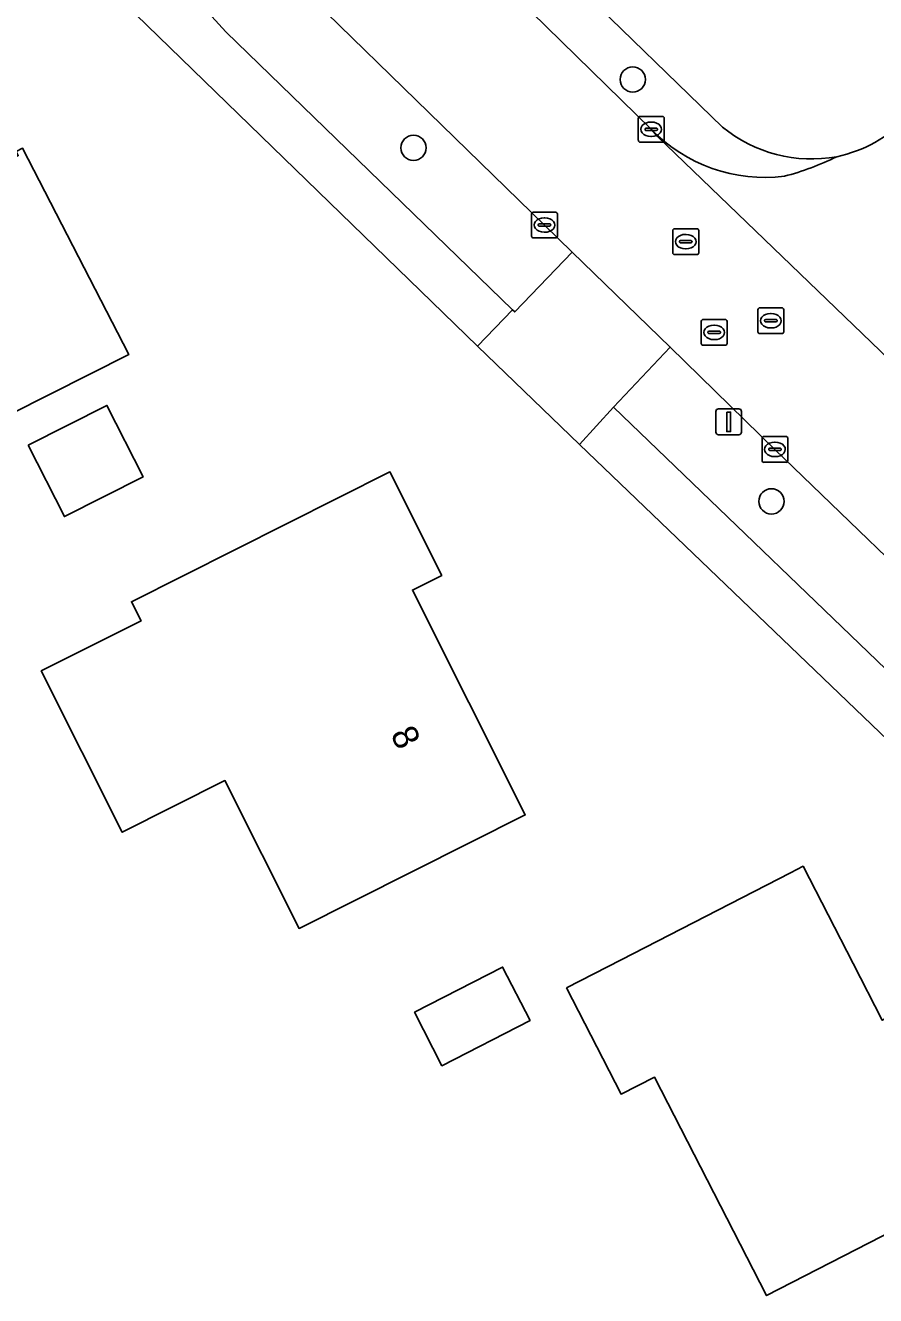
# Model space of a CAD drawing. Extents: x 162722 to 165104, y 384719 to 386284.
# Drawn here: x 163705.77 to 163738.67, y 384880.98 to 384930.12 of the extents above; entities that cross this region are included whole.
import ezdxf

# ---------------------------------------------------------------- set-up
doc = ezdxf.new("R2010")
doc.units = 0
for name, color, linetype in [('IMGEO_Boom', 7, 'Continuous'), ('IMGEO_Erf', 7, 'Continuous'), ('IMGEO_Groenvoorziening', 7, 'Continuous'), ('IMGEO_Kolk', 7, 'Continuous'), ('IMGEO_Lichtmast', 7, 'Continuous'), ('IMGEO_Pand', 7, 'Continuous'), ('IMGEO_Pand_nummerreeks', 7, 'Continuous'), ('IMGEO_Parkeervlak_open', 7, 'Continuous'), ('IMGEO_Rijbaan_lokaal_open', 7, 'Continuous'), ('IMGEO_Rioolput', 7, 'Continuous'), ('IMGEO_Voetpad_open', 7, 'Continuous')]:
    doc.layers.add(name, color=color, linetype=linetype)

msp = doc.modelspace()

# ---------------------------------------------------------------- linework, layer by layer
at = {"layer": 'IMGEO_Boom'}
for centre in [(163729.27, 384928.029), (163720.787, 384925.386), (163734.636, 384911.709)]:
    msp.add_circle(centre, 0.489, dxfattribs=at)
at = {"layer": 'IMGEO_Erf'}
for points in [[(163743.466, 384898.114), (163739.775, 384901.866), (163727.21, 384913.912), (163723.266, 384917.713), (163708.711, 384931.843), (163707.497, 384933.071), (163703.684, 384937.056), (163680.028, 384919.248)], [(163721.477, 384937.136), (163732.746, 384926.182)]]:
    msp.add_lwpolyline(points, dxfattribs=at)
for points in [[(163700.576, 384912.76), (163698.165, 384917.548), (163690.367, 384913.622), (163687.312, 384919.691), (163692.94, 384922.524), (163693.071, 384922.265), (163695.08, 384923.277), (163694.949, 384923.535), (163702.295, 384927.318), (163703.875, 384924.249), (163705.494, 384925.083), (163705.411, 384925.243), (163705.661, 384925.37), (163709.772, 384917.389)], [(163705.88, 384913.883), (163708.922, 384915.423), (163710.322, 384912.657), (163707.28, 384911.117)], [(163716.362, 384895.186), (163713.493, 384900.904), (163709.515, 384898.909), (163706.384, 384905.149), (163710.244, 384907.086), (163709.872, 384907.826), (163719.873, 384912.845), (163721.881, 384908.845), (163720.746, 384908.276), (163725.112, 384899.577)], [(163726.707, 384892.894), (163728.818, 384893.978), (163735.374, 384897.343), (163735.863, 384897.594), (163737.794, 384893.832), (163738.923, 384891.634), (163740.951, 384892.675), (163744.345, 384886.063), (163734.448, 384880.983), (163730.109, 384889.438), (163728.82, 384888.776)], [(163724.237, 384893.694), (163725.297, 384891.628), (163721.888, 384889.878), (163720.828, 384891.944)]]:
    msp.add_lwpolyline(points, close=True, dxfattribs=at)
for centre, radius, start, end in [((163735.945, 384930.498), 5.594, 282.6076, 314.948), ((163736.202, 384930.43), 5.476, 230.8666, 280.1356)]:
    msp.add_arc(centre, radius, start, end, dxfattribs=at)
at = {"layer": 'IMGEO_Groenvoorziening'}
msp.add_lwpolyline([(163706.129, 384938.825), (163705.921, 384938.688), (163709.613, 384934.17), (163713.526, 384929.868), (163724.619, 384919.117), (163724.703, 384919.039), (163726.925, 384921.347), (163725.854, 384922.399), (163712.452, 384935.454), (163709.401, 384938.391)], dxfattribs=at)
msp.add_lwpolyline([(163743.27, 384905.487), (163742.334, 384906.411), (163734.773, 384913.719), (163730.72, 384917.677), (163728.529, 384915.354), (163741.103, 384903.254)], close=True, dxfattribs=at)
at = {"layer": 'IMGEO_Kolk'}
for p, q in [((163729.486, 384925.677), (163729.486, 384926.529)), ((163729.561, 384926.603), (163730.413, 384926.603)), ((163730.487, 384926.529), (163730.487, 384925.677)), ((163729.745, 384926.097), (163729.745, 384926.109)), ((163730.183, 384926.06), (163729.785, 384926.06)), ((163729.788, 384926.146), (163730.186, 384926.146)), ((163729.974, 384926.383), (163729.999, 384926.383)), ((163730.229, 384926.109), (163730.229, 384926.097)), ((163730.413, 384925.603), (163729.561, 384925.603)), ((163729.997, 384925.823), (163729.972, 384925.823)), ((163725.353, 384921.973), (163725.353, 384922.825)), ((163725.428, 384922.899), (163726.28, 384922.899)), ((163725.841, 384922.679), (163725.866, 384922.679)), ((163726.354, 384922.825), (163726.354, 384921.973)), ((163725.612, 384922.393), (163725.612, 384922.405)), ((163726.05, 384922.356), (163725.652, 384922.356)), ((163725.655, 384922.442), (163726.053, 384922.442)), ((163725.864, 384922.119), (163725.839, 384922.119)), ((163726.096, 384922.405), (163726.096, 384922.393)), ((163726.28, 384921.899), (163725.428, 384921.899)), ((163734.272, 384913.293), (163734.272, 384914.145)), ((163734.347, 384914.219), (163735.199, 384914.219)), ((163735.273, 384914.145), (163735.273, 384913.293)), ((163734.531, 384913.713), (163734.531, 384913.725)), ((163734.969, 384913.676), (163734.571, 384913.676)), ((163734.574, 384913.762), (163734.972, 384913.762)), ((163734.76, 384913.999), (163734.785, 384913.999)), ((163735.015, 384913.725), (163735.015, 384913.713)), ((163735.199, 384913.219), (163734.347, 384913.219)), ((163734.783, 384913.439), (163734.758, 384913.439))]:
    msp.add_line(p, q, dxfattribs=at)
for points in [[(163729.486, 384925.677), (163729.486, 384926.529)], [(163729.561, 384926.603), (163730.413, 384926.603)], [(163730.487, 384926.529), (163730.487, 384925.677)], [(163730.413, 384925.603), (163729.561, 384925.603)], [(163725.353, 384921.973), (163725.353, 384922.825)], [(163725.428, 384922.899), (163726.28, 384922.899)], [(163726.354, 384922.825), (163726.354, 384921.973)], [(163726.28, 384921.899), (163725.428, 384921.899)], [(163734.272, 384913.293), (163734.272, 384914.145)], [(163734.347, 384914.219), (163735.199, 384914.219)], [(163735.273, 384914.145), (163735.273, 384913.293)], [(163735.199, 384913.219), (163734.347, 384913.219)]]:
    msp.add_lwpolyline(points, dxfattribs=at)
for centre, radius, start, end in [((163729.563, 384926.527), 0.0765, 91.552, 178.448), ((163729.563, 384926.527), 0.0765, 91.552, 178.448), ((163730.411, 384926.527), 0.0765, 1.552, 88.448), ((163730.411, 384926.527), 0.0765, 1.552, 88.448), ((163729.785, 384926.106), 0.0403, 85.8775, 175.7526), ((163729.782, 384926.096), 0.0366, 178.938, 274.7102), ((163730.186, 384926.103), 0.043, 264.8664, 352.4533), ((163730.19, 384926.108), 0.0386, 1.7309, 96.639), ((163729.563, 384925.679), 0.0765, 181.552, 268.448), ((163729.563, 384925.679), 0.0765, 181.552, 268.448), ((163730.411, 384925.679), 0.0765, 271.552, 358.448), ((163730.411, 384925.679), 0.0765, 271.552, 358.448), ((163725.43, 384922.823), 0.0765, 91.552, 178.448), ((163725.43, 384922.823), 0.0765, 91.552, 178.448), ((163726.278, 384922.823), 0.0765, 1.552, 88.448), ((163726.278, 384922.823), 0.0765, 1.552, 88.448), ((163725.652, 384922.402), 0.0403, 85.8775, 175.7526), ((163725.649, 384922.392), 0.0366, 178.938, 274.7102), ((163726.053, 384922.399), 0.043, 264.8664, 352.4533), ((163726.057, 384922.404), 0.0386, 1.7309, 96.639), ((163725.43, 384921.975), 0.0765, 181.552, 268.448), ((163725.43, 384921.975), 0.0765, 181.552, 268.448), ((163726.278, 384921.975), 0.0765, 271.552, 358.448), ((163726.278, 384921.975), 0.0765, 271.552, 358.448), ((163734.349, 384914.143), 0.0765, 91.552, 178.448), ((163734.349, 384914.143), 0.0765, 91.552, 178.448), ((163735.197, 384914.143), 0.0765, 1.552, 88.448), ((163735.197, 384914.143), 0.0765, 1.552, 88.448), ((163734.571, 384913.722), 0.0403, 85.8775, 175.7526), ((163734.568, 384913.712), 0.0366, 178.938, 274.7102), ((163734.972, 384913.719), 0.043, 264.8664, 352.4533), ((163734.976, 384913.724), 0.0386, 1.7309, 96.639), ((163734.349, 384913.295), 0.0765, 181.552, 268.448), ((163734.349, 384913.295), 0.0765, 181.552, 268.448), ((163735.197, 384913.295), 0.0765, 271.552, 358.448), ((163735.197, 384913.295), 0.0765, 271.552, 358.448)]:
    msp.add_arc(centre, radius, start, end, dxfattribs=at)
for centre, major_axis, ratio, start_param, end_param in [((163729.973, 384926.103), (-0.387, 0.002), 0.722429, 4.712389, 7.853982), ((163729.998, 384926.103), (-0.39, 0.002), 0.717154, 1.570796, 4.712389), ((163725.84, 384922.399), (-0.387, 0.002), 0.722429, 4.712389, 7.853982), ((163725.865, 384922.399), (-0.39, 0.002), 0.717154, 1.570796, 4.712389), ((163734.759, 384913.719), (-0.387, 0.002), 0.722429, 4.712389, 7.853982), ((163734.784, 384913.719), (-0.39, 0.002), 0.717154, 1.570796, 4.712389)]:
    msp.add_ellipse(centre, major_axis=major_axis, ratio=ratio, start_param=start_param, end_param=end_param, dxfattribs=at)
at = {"layer": 'IMGEO_Lichtmast'}
for p, q in [((163732.487, 384914.386), (163732.487, 384915.186)), ((163732.487, 384915.186), (163732.487, 384914.386)), ((163732.587, 384915.286), (163733.377, 384915.286)), ((163733.377, 384915.286), (163732.587, 384915.286)), ((163733.477, 384915.186), (163733.477, 384914.386)), ((163733.477, 384914.386), (163733.477, 384915.186)), ((163733.377, 384914.286), (163732.587, 384914.286)), ((163732.587, 384914.286), (163733.377, 384914.286))]:
    msp.add_line(p, q, dxfattribs=at)
msp.add_lwpolyline([(163732.907, 384915.161), (163733.057, 384915.161), (163733.057, 384914.411), (163732.907, 384914.411), (163732.907, 384915.161)], dxfattribs=at)
for centre, start, end in [((163732.587, 384915.186), 90, 180), ((163732.587, 384915.186), 90, 180), ((163733.377, 384915.186), 0, 90), ((163733.377, 384915.186), 360, 90), ((163732.587, 384914.386), 180, 270), ((163732.587, 384914.386), 180, 270), ((163733.377, 384914.386), 270, 0), ((163733.377, 384914.386), 270, 0)]:
    msp.add_arc(centre, 0.1, start, end, dxfattribs=at)
at = {"layer": 'IMGEO_Pand'}
for points in [[(163694.949, 384923.535), (163695.08, 384923.277), (163693.071, 384922.265), (163692.94, 384922.524), (163687.312, 384919.691), (163690.367, 384913.622), (163698.165, 384917.548), (163700.576, 384912.76), (163709.772, 384917.389), (163705.661, 384925.37), (163705.411, 384925.243), (163705.494, 384925.083), (163703.875, 384924.249), (163702.295, 384927.318)], [(163705.88, 384913.883), (163707.28, 384911.117), (163710.322, 384912.657), (163708.922, 384915.423)], [(163725.112, 384899.577), (163720.746, 384908.276), (163721.881, 384908.845), (163719.873, 384912.845), (163709.872, 384907.826), (163710.244, 384907.086), (163706.384, 384905.149), (163709.515, 384898.909), (163713.493, 384900.904), (163716.362, 384895.186)], [(163726.707, 384892.894), (163728.82, 384888.776), (163730.109, 384889.438), (163734.448, 384880.983), (163744.345, 384886.063), (163740.951, 384892.675), (163738.923, 384891.634), (163737.794, 384893.832), (163735.863, 384897.594), (163735.374, 384897.343), (163728.818, 384893.978)], [(163720.828, 384891.944), (163721.888, 384889.878), (163725.297, 384891.628), (163724.237, 384893.694)]]:
    msp.add_lwpolyline(points, close=True, dxfattribs=at)
at = {"layer": 'IMGEO_Parkeervlak_open'}
msp.add_lwpolyline([(163732.746, 384926.182), (163721.477, 384937.136), (163720.131, 384935.757), (163729.987, 384926.103)], dxfattribs=at)
for centre, radius, start, end in [((163734.383, 384930.362), 6.121, 224.0915, 277.0947), ((163736.202, 384930.43), 5.476, 230.8666, 280.1356), ((163732.389, 384934.822), 10.887, 284.6322, 296.0269)]:
    msp.add_arc(centre, radius, start, end, dxfattribs=at)
at = {"layer": 'IMGEO_Rijbaan_lokaal_open'}
for points in [[(163729.987, 384926.103), (163720.131, 384935.757), (163717.931, 384937.92), (163716.552, 384939.414), (163715.161, 384941.031)], [(163712.452, 384935.454), (163725.854, 384922.399), (163726.925, 384921.347), (163730.72, 384917.677), (163734.773, 384913.719), (163742.334, 384906.411), (163743.27, 384905.487), (163747.074, 384901.756), (163754.848, 384894.139), (163760.946, 384888.265)], [(163767.038, 384890.055), (163760.158, 384896.76), (163755.5, 384901.311), (163743.694, 384912.858), (163742.747, 384913.794), (163742.638, 384913.882), (163730.224, 384925.82), (163729.987, 384926.103)], [(163729.987, 384926.103), (163730.224, 384925.82), (163742.638, 384913.882), (163742.747, 384913.794)]]:
    msp.add_lwpolyline(points, dxfattribs=at)
for centre, radius, start, end in [((163735.945, 384930.498), 5.594, 282.6076, 314.948), ((163734.383, 384930.362), 6.121, 224.0915, 277.0947), ((163732.389, 384934.822), 10.887, 284.6322, 296.0269)]:
    msp.add_arc(centre, radius, start, end, dxfattribs=at)
at = {"layer": 'IMGEO_Rioolput'}
for p, q in [((163730.82, 384921.33), (163730.82, 384922.182)), ((163730.895, 384922.256), (163731.747, 384922.256)), ((163731.308, 384922.036), (163731.333, 384922.036)), ((163731.821, 384922.182), (163731.821, 384921.33)), ((163731.079, 384921.75), (163731.079, 384921.762)), ((163731.517, 384921.713), (163731.119, 384921.713)), ((163731.122, 384921.799), (163731.52, 384921.799)), ((163731.563, 384921.762), (163731.563, 384921.75)), ((163731.747, 384921.256), (163730.895, 384921.256)), ((163731.331, 384921.476), (163731.306, 384921.476)), ((163734.114, 384918.271), (163734.114, 384919.123)), ((163734.189, 384919.197), (163735.041, 384919.197)), ((163735.115, 384919.123), (163735.115, 384918.271)), ((163731.922, 384917.82), (163731.922, 384918.672)), ((163731.997, 384918.746), (163732.849, 384918.746)), ((163732.923, 384918.672), (163732.923, 384917.82)), ((163734.373, 384918.691), (163734.373, 384918.703)), ((163734.811, 384918.654), (163734.413, 384918.654)), ((163734.416, 384918.74), (163734.814, 384918.74)), ((163734.602, 384918.977), (163734.627, 384918.977)), ((163734.857, 384918.703), (163734.857, 384918.691)), ((163732.181, 384918.24), (163732.181, 384918.252)), ((163732.619, 384918.203), (163732.221, 384918.203)), ((163732.224, 384918.289), (163732.622, 384918.289)), ((163732.41, 384918.526), (163732.435, 384918.526)), ((163732.665, 384918.252), (163732.665, 384918.24)), ((163735.041, 384918.197), (163734.189, 384918.197)), ((163734.625, 384918.417), (163734.6, 384918.417)), ((163732.849, 384917.746), (163731.997, 384917.746)), ((163732.433, 384917.966), (163732.408, 384917.966))]:
    msp.add_line(p, q, dxfattribs=at)
for points in [[(163730.82, 384921.33), (163730.82, 384922.182)], [(163730.895, 384922.256), (163731.747, 384922.256)], [(163731.821, 384922.182), (163731.821, 384921.33)], [(163731.747, 384921.256), (163730.895, 384921.256)], [(163734.114, 384918.271), (163734.114, 384919.123)], [(163734.189, 384919.197), (163735.041, 384919.197)], [(163735.115, 384919.123), (163735.115, 384918.271)], [(163731.922, 384917.82), (163731.922, 384918.672)], [(163731.997, 384918.746), (163732.849, 384918.746)], [(163732.923, 384918.672), (163732.923, 384917.82)], [(163735.041, 384918.197), (163734.189, 384918.197)], [(163732.849, 384917.746), (163731.997, 384917.746)]]:
    msp.add_lwpolyline(points, dxfattribs=at)
for centre, radius, start, end in [((163730.897, 384922.18), 0.0765, 91.552, 178.448), ((163730.897, 384922.18), 0.0765, 91.552, 178.448), ((163731.745, 384922.18), 0.0765, 1.552, 88.448), ((163731.745, 384922.18), 0.0765, 1.552, 88.448), ((163731.119, 384921.759), 0.0403, 85.8775, 175.7526), ((163731.116, 384921.749), 0.0366, 178.938, 274.7102), ((163731.52, 384921.756), 0.043, 264.8664, 352.4533), ((163731.524, 384921.761), 0.0386, 1.7309, 96.639), ((163730.897, 384921.332), 0.0765, 181.552, 268.448), ((163730.897, 384921.332), 0.0765, 181.552, 268.448), ((163731.745, 384921.332), 0.0765, 271.552, 358.448), ((163731.745, 384921.332), 0.0765, 271.552, 358.448), ((163734.191, 384919.121), 0.0765, 91.552, 178.448), ((163734.191, 384919.121), 0.0765, 91.552, 178.448), ((163735.039, 384919.121), 0.0765, 1.552, 88.448), ((163735.039, 384919.121), 0.0765, 1.552, 88.448), ((163731.999, 384918.67), 0.0765, 91.552, 178.448), ((163731.999, 384918.67), 0.0765, 91.552, 178.448), ((163732.847, 384918.67), 0.0765, 1.552, 88.448), ((163732.847, 384918.67), 0.0765, 1.552, 88.448), ((163734.413, 384918.7), 0.0403, 85.8775, 175.7526), ((163734.41, 384918.69), 0.0366, 178.938, 274.7102), ((163734.814, 384918.697), 0.043, 264.8664, 352.4533), ((163734.818, 384918.702), 0.0386, 1.7309, 96.639), ((163732.221, 384918.249), 0.0403, 85.8775, 175.7526), ((163732.218, 384918.239), 0.0366, 178.938, 274.7102), ((163732.622, 384918.246), 0.043, 264.8664, 352.4533), ((163732.626, 384918.251), 0.0386, 1.7309, 96.639), ((163734.191, 384918.273), 0.0765, 181.552, 268.448), ((163734.191, 384918.273), 0.0765, 181.552, 268.448), ((163735.039, 384918.273), 0.0765, 271.552, 358.448), ((163735.039, 384918.273), 0.0765, 271.552, 358.448), ((163731.999, 384917.822), 0.0765, 181.552, 268.448), ((163731.999, 384917.822), 0.0765, 181.552, 268.448), ((163732.847, 384917.822), 0.0765, 271.552, 358.448), ((163732.847, 384917.822), 0.0765, 271.552, 358.448)]:
    msp.add_arc(centre, radius, start, end, dxfattribs=at)
for centre, major_axis, ratio, start_param, end_param in [((163731.307, 384921.756), (-0.387, 0.002), 0.722429, 4.712389, 7.853982), ((163731.332, 384921.756), (-0.39, 0.002), 0.717154, 1.570796, 4.712389), ((163734.601, 384918.697), (-0.387, 0.002), 0.722429, 4.712389, 7.853982), ((163734.626, 384918.697), (-0.39, 0.002), 0.717154, 1.570796, 4.712389), ((163732.409, 384918.246), (-0.387, 0.002), 0.722429, 4.712389, 7.853982), ((163732.434, 384918.246), (-0.39, 0.002), 0.717154, 1.570796, 4.712389)]:
    msp.add_ellipse(centre, major_axis=major_axis, ratio=ratio, start_param=start_param, end_param=end_param, dxfattribs=at)
at = {"layer": 'IMGEO_Voetpad_open'}
for points in [[(163705.921, 384938.688), (163705.755, 384938.594), (163703.684, 384937.056), (163707.497, 384933.071), (163708.711, 384931.843), (163723.266, 384917.713), (163724.619, 384919.117), (163713.526, 384929.868), (163709.613, 384934.17)], [(163730.72, 384917.677), (163726.925, 384921.347), (163724.703, 384919.039), (163724.619, 384919.117), (163723.266, 384917.713), (163727.21, 384913.912), (163728.529, 384915.354)], [(163728.529, 384915.354), (163727.21, 384913.912), (163739.775, 384901.866), (163741.103, 384903.254)]]:
    msp.add_lwpolyline(points, close=True, dxfattribs=at)

# ---------------------------------------------------------------- texts
at = {"layer": 'IMGEO_Pand_nummerreeks'}
msp.add_text('8', height=1, rotation=296.6519, dxfattribs=at).set_placement((163719.876, 384902.699))

doc.saveas('drawing.dxf')
